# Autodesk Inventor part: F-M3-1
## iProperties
FINISH: PASSIVATE
Author: RON
Shininess: 64.0
Angle Display Precision: 2
Document Length Units: 11269
Document Angle Units: 11284
Document Time Units: 11279
Document Mass Units: 11290
Document Length Units Precision: 3
Document Angle Units Precision: 2
Compacted: True
PropertySet Name: _Private Model Information
Created: 2002-07
Part Number: F-M3-1
Material: 303 SST
Description: FASTENER, SELF CLINCH, FLUSH, M3
Vendor: PENN ENG & MFG
Document SubType Name: Modeling
Designer: RON
Control State: 0
Master: False
Checked Out: False
PropertySet Name: Design Tracking Control
Density: 0.0
Volumn: 0.0
Area: 0.0
PropertySet Name: Model Information
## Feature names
1. Extrusion1
2. Extrusion2
